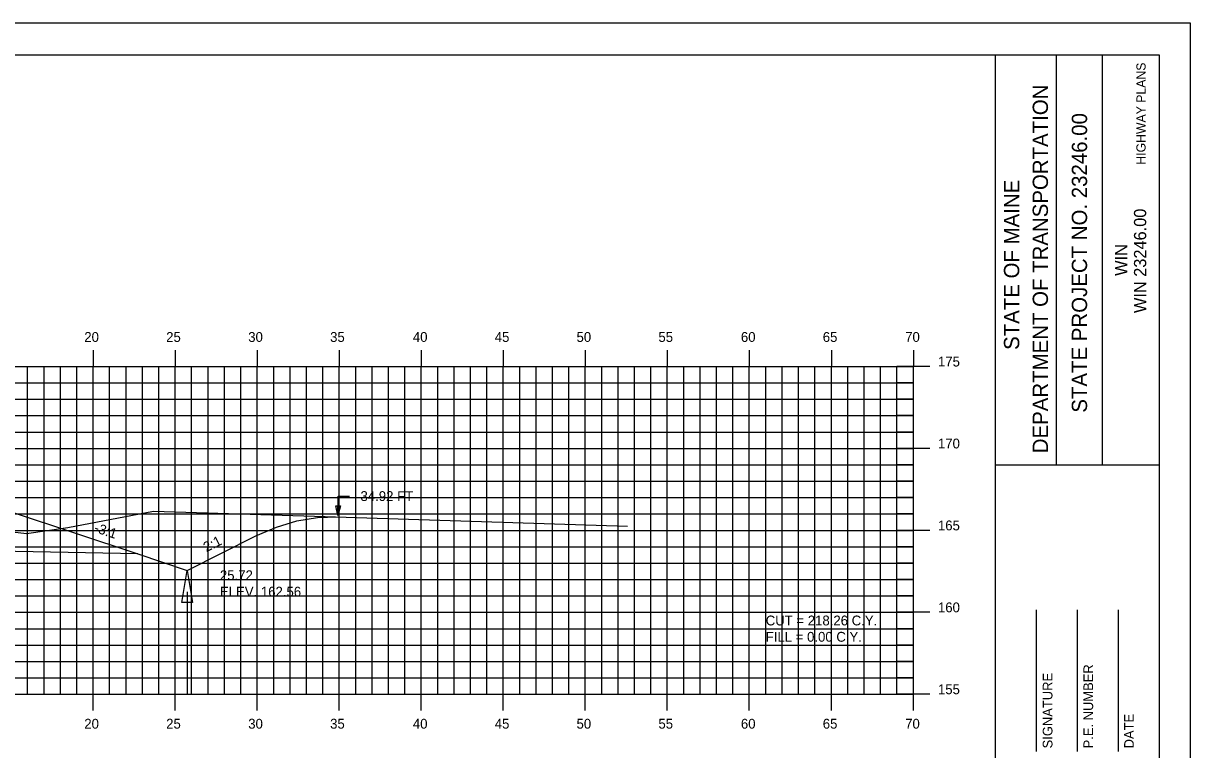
# Model space of a CAD drawing. Extents: x 1142311 to 1142481, y 608981 to 609091.
# Drawn here: x 1142410 to 1142481.2, y 609047 to 609091.3 of the extents above; entities that cross this region are included whole.
import ezdxf

# ---------------------------------------------------------------- set-up
doc = ezdxf.new("R2010")
doc.units = 0
for name, color, linetype in [('ANNOTATION', 7, 'Continuous'), ('BORDER', 7, 'Continuous'), ('D_Drainage_Ditch_Line', 7, 'Continuous'), ('D_Roadway_SlopeLines', 7, 'Continuous'), ('D_Roadway_SubGrade', 7, 'Continuous'), ('D_Text_Standard', 7, 'Continuous'), ('H_V ANNOTATION', 7, 'Continuous'), ('HIGHWAY_TITLE', 7, 'Continuous'), ('MAJOR', 7, 'Continuous'), ('MINOR', 7, 'Continuous'), ('PLOT BOUNDARY', 7, 'Continuous'), ('S_Roadway_Centerline', 7, 'Continuous')]:
    doc.layers.add(name, color=color, linetype=linetype)

msp = doc.modelspace()

# ---------------------------------------------------------------- linework, layer by layer
msp.add_lwpolyline([(1142360.44, 609060.945), (1142361.69, 609060.764), (1142362.94, 609060.457), (1142364.19, 609060.022), (1142365.44, 609059.46), (1142368.572, 609057.894), (1142371.572, 609058.894), (1142379.296, 609061.469), (1142379.297, 609061.469), (1142383.297, 609061.629), (1142394.297, 609061.849), (1142405.297, 609061.629), (1142409.297, 609061.469), (1142417.02, 609058.895), (1142420.02, 609057.895), (1142424.217, 609059.993), (1142425.467, 609060.535), (1142426.717, 609060.911), (1142427.967, 609061.121), (1142429.217, 609061.165)])
at = {"layer": 'BORDER'}
for p, q in [((1142469.297, 608984.335), (1142469.297, 609089.335)), ((1142473.026, 609064.332), (1142473.026, 609089.332)), ((1142475.821, 609064.332), (1142475.821, 609089.332)), ((1142469.298, 609064.329), (1142479.297, 609064.329)), ((1142471.797, 609046.838), (1142471.797, 609055.485)), ((1142474.297, 609046.838), (1142474.297, 609055.485)), ((1142476.797, 609046.838), (1142476.797, 609055.485))]:
    msp.add_line(p, q, dxfattribs=at)
msp.add_lwpolyline([(1142319.297, 608984.335), (1142479.297, 608984.335), (1142479.297, 609089.335), (1142319.297, 609089.335)], close=True, dxfattribs=at)
at = {"layer": 'D_Drainage_Ditch_Line'}
msp.add_line((1142420.02, 609056.582), (1142420.02, 609050.339), dxfattribs=at)
msp.add_lwpolyline([(1142420.348, 609055.926), (1142419.692, 609055.926), (1142420.02, 609057.895)], close=True, dxfattribs=at)
at = {"layer": 'D_Roadway_SlopeLines'}
for points in [[(1142420.02, 609057.895), (1142424.217, 609059.993), (1142425.467, 609060.535), (1142426.717, 609060.911), (1142427.967, 609061.121), (1142429.217, 609061.165)], [(1142417.02, 609058.895), (1142420.02, 609057.895)]]:
    msp.add_lwpolyline(points, dxfattribs=at)
at = {"layer": 'D_Roadway_SubGrade'}
msp.add_lwpolyline([(1142405.297, 609061.212), (1142405.297, 609061.379), (1142409.297, 609061.219), (1142409.297, 609061.469), (1142409.297, 609061.469), (1142417.02, 609058.895), (1142405.297, 609059.129)], close=True, dxfattribs=at)
at = {"layer": 'D_Text_Standard'}
msp.add_lwpolyline([(1142429.217, 609061.243), (1142429.231, 609062.426), (1142429.911, 609062.426)], dxfattribs=at)
msp.add_lwpolyline([(1142429.217, 609061.243), (1142429.078, 609061.826), (1142429.369, 609061.823)], close=True, dxfattribs=at)
at = {"layer": 'MAJOR'}
for p, q in [((1142414.297, 609071.337), (1142414.297, 609070.335)), ((1142419.297, 609071.337), (1142419.297, 609070.335)), ((1142424.297, 609071.337), (1142424.297, 609070.335)), ((1142429.297, 609071.337), (1142429.297, 609070.335)), ((1142434.297, 609071.337), (1142434.297, 609070.335)), ((1142439.297, 609071.337), (1142439.297, 609070.335)), ((1142444.297, 609071.337), (1142444.297, 609070.335)), ((1142449.297, 609071.337), (1142449.297, 609070.335)), ((1142454.297, 609071.337), (1142454.297, 609070.335)), ((1142459.297, 609071.337), (1142459.297, 609070.335)), ((1142464.297, 609071.337), (1142464.297, 609070.335)), ((1142324.297, 609070.335), (1142464.297, 609070.335)), ((1142324.297, 609070.335), (1142464.297, 609070.335)), ((1142414.297, 609050.335), (1142414.297, 609070.335)), ((1142419.297, 609050.335), (1142419.297, 609070.335)), ((1142424.297, 609050.335), (1142424.297, 609070.335)), ((1142429.297, 609050.335), (1142429.297, 609070.335)), ((1142434.297, 609050.335), (1142434.297, 609070.335)), ((1142439.297, 609050.335), (1142439.297, 609070.335)), ((1142444.297, 609050.335), (1142444.297, 609070.335)), ((1142449.297, 609050.335), (1142449.297, 609070.335)), ((1142454.297, 609050.335), (1142454.297, 609070.335)), ((1142459.297, 609050.335), (1142459.297, 609070.335)), ((1142465.299, 609070.335), (1142463.295, 609070.335)), ((1142464.297, 609050.335), (1142464.297, 609070.335)), ((1142464.297, 609050.335), (1142464.297, 609070.335)), ((1142324.297, 609065.335), (1142464.297, 609065.335)), ((1142465.299, 609065.335), (1142463.295, 609065.335)), ((1142324.297, 609060.335), (1142464.297, 609060.335)), ((1142465.299, 609060.335), (1142463.295, 609060.335)), ((1142324.297, 609055.335), (1142464.297, 609055.335)), ((1142465.299, 609055.335), (1142463.295, 609055.335)), ((1142324.297, 609050.335), (1142464.297, 609050.335)), ((1142324.297, 609050.335), (1142464.297, 609050.335)), ((1142414.297, 609049.333), (1142414.297, 609050.335)), ((1142419.297, 609049.333), (1142419.297, 609050.335)), ((1142424.297, 609049.333), (1142424.297, 609050.335)), ((1142429.297, 609049.333), (1142429.297, 609050.335)), ((1142434.297, 609049.333), (1142434.297, 609050.335)), ((1142439.297, 609049.333), (1142439.297, 609050.335)), ((1142444.297, 609049.333), (1142444.297, 609050.335)), ((1142449.297, 609049.333), (1142449.297, 609050.335)), ((1142454.297, 609049.333), (1142454.297, 609050.335)), ((1142459.297, 609049.333), (1142459.297, 609050.335)), ((1142465.299, 609050.335), (1142463.295, 609050.335)), ((1142464.297, 609049.333), (1142464.297, 609050.335))]:
    msp.add_line(p, q, dxfattribs=at)
at = {"layer": 'MINOR'}
for p, q in [((1142410.297, 609050.335), (1142410.297, 609070.335)), ((1142411.297, 609050.335), (1142411.297, 609070.335)), ((1142412.297, 609050.335), (1142412.297, 609070.335)), ((1142413.297, 609050.335), (1142413.297, 609070.335)), ((1142415.297, 609050.335), (1142415.297, 609070.335)), ((1142416.297, 609050.335), (1142416.297, 609070.335)), ((1142417.297, 609050.335), (1142417.297, 609070.335)), ((1142418.297, 609050.335), (1142418.297, 609070.335)), ((1142420.297, 609050.335), (1142420.297, 609070.335)), ((1142421.297, 609050.335), (1142421.297, 609070.335)), ((1142422.297, 609050.335), (1142422.297, 609070.335)), ((1142423.297, 609050.335), (1142423.297, 609070.335)), ((1142425.297, 609050.335), (1142425.297, 609070.335)), ((1142426.297, 609050.335), (1142426.297, 609070.335)), ((1142427.297, 609050.335), (1142427.297, 609070.335)), ((1142428.297, 609050.335), (1142428.297, 609070.335)), ((1142430.297, 609050.335), (1142430.297, 609070.335)), ((1142431.297, 609050.335), (1142431.297, 609070.335)), ((1142432.297, 609050.335), (1142432.297, 609070.335)), ((1142433.297, 609050.335), (1142433.297, 609070.335)), ((1142435.297, 609050.335), (1142435.297, 609070.335)), ((1142436.297, 609050.335), (1142436.297, 609070.335)), ((1142437.297, 609050.335), (1142437.297, 609070.335)), ((1142438.297, 609050.335), (1142438.297, 609070.335)), ((1142440.297, 609050.335), (1142440.297, 609070.335)), ((1142441.297, 609050.335), (1142441.297, 609070.335)), ((1142442.297, 609050.335), (1142442.297, 609070.335)), ((1142443.297, 609050.335), (1142443.297, 609070.335)), ((1142445.297, 609050.335), (1142445.297, 609070.335)), ((1142446.297, 609050.335), (1142446.297, 609070.335)), ((1142447.297, 609050.335), (1142447.297, 609070.335)), ((1142448.297, 609050.335), (1142448.297, 609070.335)), ((1142450.297, 609050.335), (1142450.297, 609070.335)), ((1142451.297, 609050.335), (1142451.297, 609070.335)), ((1142452.297, 609050.335), (1142452.297, 609070.335)), ((1142453.297, 609050.335), (1142453.297, 609070.335)), ((1142455.297, 609050.335), (1142455.297, 609070.335)), ((1142456.297, 609050.335), (1142456.297, 609070.335)), ((1142457.297, 609050.335), (1142457.297, 609070.335)), ((1142458.297, 609050.335), (1142458.297, 609070.335)), ((1142460.297, 609050.335), (1142460.297, 609070.335)), ((1142461.297, 609050.335), (1142461.297, 609070.335)), ((1142462.297, 609050.335), (1142462.297, 609070.335)), ((1142463.297, 609050.335), (1142463.297, 609070.335)), ((1142324.297, 609069.335), (1142464.297, 609069.335)), ((1142464.297, 609069.335), (1142463.295, 609069.335)), ((1142324.297, 609068.335), (1142464.297, 609068.335)), ((1142464.297, 609068.335), (1142463.295, 609068.335)), ((1142324.297, 609067.335), (1142464.297, 609067.335)), ((1142464.297, 609067.335), (1142463.295, 609067.335)), ((1142324.297, 609066.335), (1142464.297, 609066.335)), ((1142464.297, 609066.335), (1142463.295, 609066.335)), ((1142324.297, 609064.335), (1142464.297, 609064.335)), ((1142464.297, 609064.335), (1142463.295, 609064.335)), ((1142324.297, 609063.335), (1142464.297, 609063.335)), ((1142464.297, 609063.335), (1142463.295, 609063.335)), ((1142324.297, 609062.335), (1142464.297, 609062.335)), ((1142464.297, 609062.335), (1142463.295, 609062.335)), ((1142324.297, 609061.335), (1142464.297, 609061.335)), ((1142464.297, 609061.335), (1142463.295, 609061.335)), ((1142324.297, 609059.335), (1142464.297, 609059.335)), ((1142464.297, 609059.335), (1142463.295, 609059.335)), ((1142324.297, 609058.335), (1142464.297, 609058.335)), ((1142464.297, 609058.335), (1142463.295, 609058.335)), ((1142324.297, 609057.335), (1142464.297, 609057.335)), ((1142464.297, 609057.335), (1142463.295, 609057.335)), ((1142324.297, 609056.335), (1142464.297, 609056.335)), ((1142464.297, 609056.335), (1142463.295, 609056.335)), ((1142324.297, 609054.335), (1142464.297, 609054.335)), ((1142464.297, 609054.335), (1142463.295, 609054.335)), ((1142324.297, 609053.335), (1142464.297, 609053.335)), ((1142464.297, 609053.335), (1142463.295, 609053.335)), ((1142324.297, 609052.335), (1142464.297, 609052.335)), ((1142464.297, 609052.335), (1142463.295, 609052.335)), ((1142324.297, 609051.335), (1142464.297, 609051.335)), ((1142464.297, 609051.335), (1142463.295, 609051.335))]:
    msp.add_line(p, q, dxfattribs=at)
at = {"layer": 'PLOT BOUNDARY'}
msp.add_lwpolyline([(1142311.204, 608981.276), (1142481.204, 608981.276), (1142481.204, 609091.276), (1142311.204, 609091.276)], close=True, dxfattribs=at)
at = {"layer": 'S_Roadway_Centerline'}
msp.add_lwpolyline([(1142324.297, 609061.986), (1142327.43, 609062.024), (1142352.199, 609061.719), (1142363.18, 609060.688), (1142367.114, 609060.687), (1142370.862, 609060.287), (1142371.956, 609060.13), (1142372.66, 609060.351), (1142375.902, 609061.195), (1142376.467, 609061.226), (1142379.436, 609061.552), (1142381.746, 609061.614), (1142390.352, 609061.701), (1142392.745, 609061.612), (1142401.374, 609061.166), (1142404.67, 609060.907), (1142405.628, 609060.736), (1142409.38, 609060.244), (1142410.227, 609060.138), (1142412.74, 609060.5), (1142417.98, 609061.507), (1142428.434, 609061.191), (1142446.865, 609060.587)], dxfattribs=at)

# ---------------------------------------------------------------- texts
at = {"layer": 'ANNOTATION'}
for s, rotation, p in [('-3:1', 341.56521, (1142414.308, 609060.253)), ('2:1', 26.56505, (1142421.191, 609058.998))]:
    msp.add_text(s, height=0.6, rotation=rotation, dxfattribs=at).set_placement(p)
at = {"layer": 'BORDER'}
for s, height, p in [('DEPARTMENT OF TRANSPORTATION', 0.93176, (1142472.504, 609065.041)), ('STATE PROJECT NO. 23246.00', 0.93176, (1142474.889, 609067.517)), ('STATE OF MAINE', 0.93176, (1142470.752, 609071.347)), ('WIN 23246.00', 0.74527, (1142478.493, 609073.596)), ('WIN', 0.7453, (1142477.334, 609075.865)), ('P.E. NUMBER', 0.59055, (1142475.258, 609047.03)), ('SIGNATURE', 0.5906, (1142472.778, 609047.03)), ('DATE', 0.5906, (1142477.738, 609047.03))]:
    msp.add_text(s, height=height, rotation=90, dxfattribs=at).set_placement(p)
at = {"layer": 'D_Text_Standard'}
for s, p in [('34.92 FT', (1142430.591, 609062.126)), ('25.72', (1142422.02, 609057.295)), ('ELEV. 162.56', (1142422.02, 609056.293)), ('CUT = 218.26 C.Y.', (1142455.297, 609054.535)), ('FILL = 0.00 C.Y.', (1142455.297, 609053.539))]:
    msp.add_text(s, height=0.6, dxfattribs=at).set_placement(p)
at = {"layer": 'H_V ANNOTATION'}
for s, p in [('20', (1142413.751, 609071.835)), ('25', (1142418.743, 609071.835)), ('30', (1142423.746, 609071.835)), ('35', (1142428.738, 609071.835)), ('40', (1142433.783, 609071.835)), ('45', (1142438.775, 609071.835)), ('50', (1142443.762, 609071.835)), ('55', (1142448.754, 609071.835)), ('60', (1142453.783, 609071.835)), ('65', (1142458.775, 609071.835)), ('70', (1142463.799, 609071.835)), ('175', (1142465.797, 609070.335)), ('170', (1142465.797, 609065.335)), ('165', (1142465.797, 609060.335)), ('160', (1142465.797, 609055.335)), ('155', (1142465.797, 609050.335)), ('20', (1142413.751, 609048.235)), ('25', (1142418.743, 609048.235)), ('30', (1142423.746, 609048.235)), ('35', (1142428.738, 609048.235)), ('40', (1142433.783, 609048.235)), ('45', (1142438.775, 609048.235)), ('50', (1142443.762, 609048.235)), ('55', (1142448.754, 609048.235)), ('60', (1142453.783, 609048.235)), ('65', (1142458.775, 609048.235)), ('70', (1142463.799, 609048.235))]:
    msp.add_text(s, height=0.6, dxfattribs=at).set_placement(p)
at = {"layer": 'HIGHWAY_TITLE'}
msp.add_text('HIGHWAY PLANS', height=0.55901, rotation=90, dxfattribs=at).set_placement((1142478.455, 609082.65))

doc.saveas('drawing.dxf')
